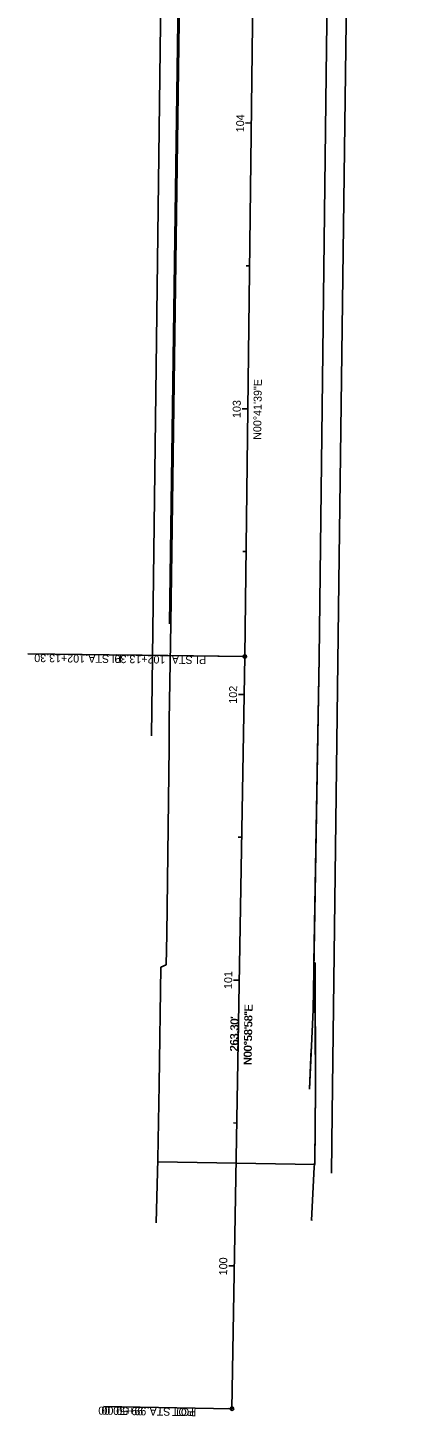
# Model space of a CAD drawing. Extents: x 1652464 to 1652601, y 605963 to 608618.
# Drawn here: x 1652463.9 to 1652601.5, y 605963.2 to 606449.1 of the extents above; entities that cross this region are included whole.
import ezdxf

# ---------------------------------------------------------------- set-up
doc = ezdxf.new("R2010")
doc.units = 0
for name, color, linetype in [('BD_X_Building', 7, 'Continuous'), ('BR_X_SV_Abut', 7, 'Continuous'), ('Default', 7, 'Continuous'), ('DR_X_Erosion_Control', 7, 'Continuous'), ('GE_X_Cells', 7, 'Continuous'), ('PV_X_Curb', 7, 'Continuous'), ('PV_X_Steps', 7, 'Continuous'), ('PV_X_Walk', 7, 'Continuous'), ('SV_P_Mon_Cells_Set', 7, 'Continuous'), ('SV_X_Control_Cells_Found', 7, 'Continuous'), ('SV_X_Shot_Marker', 7, 'Continuous'), ('UT_X_Gas', 7, 'Continuous'), ('UT_X_Water_Cells', 7, 'Continuous'), ('VG_X_Cells', 7, 'Continuous'), ('VG_X_Flower_Bed', 7, 'Continuous'), ('VG_X_Shrub_Line_Lt', 7, 'Continuous')]:
    doc.layers.add(name, color=color, linetype=linetype)

msp = doc.modelspace()

# ---------------------------------------------------------------- linework, layer by layer
at = {"layer": 'BD_X_Building'}
msp.add_lwpolyline([(1652507.27, 606201.32), (1652514.36, 606755.06), (1652515.19, 606820.32), (1652516.55, 606927.44), (1652537.47, 608602.59)], dxfattribs=at)
at = {"layer": 'Default'}
for p, q in [((1652537.06, 606057.13), (1652537.05, 606056.93)), ((1652536.99, 606053.42), (1652536.98, 606052.81))]:
    msp.add_line(p, q, dxfattribs=at)
at = {"layer": 'GE_X_Cells'}
for p, q in [((1652568.47, 606432.68), (1652569.53, 606520.3)), ((1652568.47, 606432.68), (1652569.53, 606520.3)), ((1652568.47, 606432.68), (1652569.53, 606520.3)), ((1652568.47, 606432.68), (1652569.53, 606520.3)), ((1652568.47, 606432.68), (1652569.53, 606520.3)), ((1652568.47, 606432.68), (1652569.53, 606520.3)), ((1652514.05, 606240.46), (1652517.12, 606459.77)), ((1652566, 606228.68), (1652568.47, 606432.68)), ((1652566, 606228.68), (1652568.47, 606432.68)), ((1652566, 606228.68), (1652568.47, 606432.68)), ((1652566, 606228.68), (1652568.47, 606432.68)), ((1652566, 606228.68), (1652568.47, 606432.68)), ((1652566, 606228.68), (1652568.47, 606432.68)), ((1652513.54, 606206.56), (1652514.05, 606240.46)), ((1652563.89, 606105.39), (1652566, 606228.68)), ((1652563.89, 606105.39), (1652566, 606228.68)), ((1652564.17, 606121.81), (1652566, 606228.68)), ((1652564.17, 606121.81), (1652566, 606228.68)), ((1652564.17, 606121.81), (1652566, 606228.68)), ((1652564.17, 606121.81), (1652566, 606228.68)), ((1652513.48, 606197.48), (1652513.54, 606206.56)), ((1652512.65, 606131.81), (1652513.48, 606197.48)), ((1652512.46, 606121.15), (1652512.65, 606131.81)), ((1652509.93, 606079.27), (1652510.53, 606120.34)), ((1652510.53, 606120.34), (1652512.46, 606121.15)), ((1652564.61, 606121.81), (1652564.17, 606121.81)), ((1652564.76, 606077.51), (1652564.61, 606121.81)), ((1652562.66, 606077.59), (1652563.89, 606105.39)), ((1652562.66, 606077.59), (1652563.89, 606105.39)), ((1652562.66, 606077.59), (1652563.28, 606091.74)), ((1652509.55, 606053.1), (1652509.93, 606079.27)), ((1652562.66, 606077.59), (1652562.66, 606077.68)), ((1652564.56, 606052.23), (1652564.76, 606077.51)), ((1652508.95, 606030.88), (1652509.55, 606053.1)), ((1652564.35, 606050.39), (1652564.56, 606052.23)), ((1652563.4, 606031.63), (1652564.35, 606050.39)), ((1652563.4, 606031.63), (1652563.42, 606032.07))]:
    msp.add_line(p, q, dxfattribs=at)
msp.add_lwpolyline([(1652564.55, 606051.31), (1652564.76, 606077.51), (1652564.64, 606101.8), (1652564.17, 606121.81)], dxfattribs=at)
at = {"layer": 'PV_X_Curb'}
for p, q in [((1652540.01, 606229.06), (1652551.76, 607199.34)), ((1652535.49, 605965.8), (1652540.01, 606229.06)), ((1652509.53, 606052.25), (1652564.55, 606051.31))]:
    msp.add_line(p, q, dxfattribs=at)
at = {"layer": 'PV_X_Steps'}
msp.add_lwpolyline([(1652570.42, 606048.23), (1652570.59, 606069.16), (1652572.96, 606254.92), (1652575.24, 606433.07), (1652576.4, 606523.06), (1652578.06, 606652.96), (1652579.12, 606736.34), (1652580.12, 606814.04), (1652581.65, 606935.48), (1652585.26, 607224.58), (1652586.28, 607305.92), (1652588.75, 607503.82), (1652591.34, 607710.88), (1652594.35, 607951.77), (1652594.72, 607981.92), (1652597.89, 608234.94), (1652601.47, 608521.97)], dxfattribs=at)
at = {"layer": 'PV_X_Walk'}
msp.add_line((1652513.55, 606240.47), (1652516.62, 606459.78), dxfattribs=at)
at = {"layer": 'SV_X_Control_Cells_Found'}
for p, q in [((1652540.01, 606229.06), (1652551.76, 607199.34)), ((1652540.01, 606229.06), (1652551.76, 607199.34)), ((1652535.49, 605965.8), (1652540.01, 606229.06)), ((1652535.49, 605965.8), (1652540.01, 606229.06))]:
    msp.add_line(p, q, dxfattribs=at)
at = {"layer": 'SV_X_Shot_Marker'}
for q in [(1652463.93, 606229.98), (1652495.01, 606229.6)]:
    msp.add_line((1652540.01, 606229.06), q, dxfattribs=at)
msp.add_circle((1652540.01, 606229.06), 0.6, dxfattribs=at)
msp.add_circle((1652540.01, 606229.06), 0.6, dxfattribs=at)
at = {"layer": 'UT_X_Gas'}
msp.add_line((1652535.49, 605965.8), (1652490.5, 605966.57), dxfattribs=at)
msp.add_circle((1652535.49, 605965.8), 0.6, dxfattribs=at)
at = {"layer": 'VG_X_Cells'}
for p, q in [((1652542.27, 606415.74), (1652540.27, 606415.77)), ((1652541.66, 606365.75), (1652540.46, 606365.76)), ((1652541.06, 606315.75), (1652539.06, 606315.77)), ((1652540.45, 606265.75), (1652539.25, 606265.77)), ((1652539.78, 606215.76), (1652537.78, 606215.79)), ((1652538.92, 606165.77), (1652537.72, 606165.79)), ((1652538.06, 606115.77), (1652536.06, 606115.81)), ((1652537.2, 606065.78), (1652536.01, 606065.8)), ((1652536.35, 606015.79), (1652534.35, 606015.82)), ((1652535.49, 605965.8), (1652534.29, 605965.82))]:
    msp.add_line(p, q, dxfattribs=at)
at = {"layer": 'VG_X_Flower_Bed'}
for p, q in [((1652540.01, 606229.06), (1652495.01, 606229.6)), ((1652535.49, 605965.8), (1652490.5, 605966.57))]:
    msp.add_line(p, q, dxfattribs=at)
for centre in [(1652540.01, 606229.06), (1652535.49, 605965.8)]:
    msp.add_circle(centre, 0.6, dxfattribs=at)
at = {"layer": 'VG_X_Shrub_Line_Lt'}
for p, q in [((1652542.27, 606415.74), (1652541.07, 606415.76)), ((1652541.06, 606315.75), (1652539.86, 606315.76)), ((1652539.78, 606215.76), (1652538.58, 606215.78)), ((1652538.06, 606115.77), (1652536.86, 606115.79)), ((1652536.35, 606015.79), (1652534.35, 606015.82))]:
    msp.add_line(p, q, dxfattribs=at)

# ---------------------------------------------------------------- texts
at = {"layer": 'BR_X_SV_Abut'}
msp.add_text('N00°58\'58"E', height=2.8, rotation=89.0173, dxfattribs=at).set_placement((1652542.36, 606086.17))
at = {"layer": 'DR_X_Erosion_Control'}
msp.add_text("263.30'", height=2.8, rotation=89.0173, dxfattribs=at).set_placement((1652537.59, 606090.94))
at = {"layer": 'SV_P_Mon_Cells_Set'}
for s, rotation, p in [('N00°41\'39"E', 89.3059, (1652545.72, 606304.86)), ('N00°58\'58"E', 89.0173, (1652542.35, 606085.98))]:
    msp.add_text(s, height=2.8, rotation=rotation, dxfattribs=at).set_placement(p)
at = {"layer": 'SV_X_Shot_Marker'}
for s, p in [('102+13.30', (1652484.05, 606229.69)), (' STA. ', (1652493.5, 606229.58)), ('PI', (1652496.89, 606229.54))]:
    msp.add_text(s, height=2.8, rotation=179.3059, dxfattribs=at).set_placement(p)
at = {"layer": 'UT_X_Gas'}
for s, p in [('99+50.00', (1652505.52, 605966.27)), (' STA. ', (1652514.97, 605966.11)), ('POT', (1652522.17, 605965.98))]:
    msp.add_text(s, height=2.8, rotation=179.0173, dxfattribs=at).set_placement(p)
at = {"layer": 'UT_X_Water_Cells'}
msp.add_text("263.30'", height=2.8, rotation=89.0173, dxfattribs=at).set_placement((1652537.59, 606090.75))
at = {"layer": 'VG_X_Cells'}
for s, rotation, p in [('104', 89.3059, (1652539.73, 606412.5)), ('103', 89.3059, (1652538.52, 606312.51)), ('102', 89.0173, (1652537.22, 606212.52)), ('101', 89.0173, (1652535.51, 606112.67)), ('100', 89.0173, (1652533.79, 606012.48))]:
    msp.add_text(s, height=2.8, rotation=rotation, dxfattribs=at).set_placement(p)
at = {"layer": 'VG_X_Flower_Bed'}
for s, rotation, p in [('102+13.30', 179.3059, (1652512.18, 606229.35)), (' STA. ', 179.3059, (1652522.76, 606229.22)), ('PI', 179.3059, (1652526.46, 606229.18)), ('99+50.00', 179.0173, (1652504.41, 605966.28)), (' STA. ', 179.0173, (1652514.99, 605966.1)), ('POT', 179.0173, (1652523.03, 605965.96))]:
    msp.add_text(s, height=2.8, rotation=rotation, dxfattribs=at).set_placement(p)
at = {"layer": 'VG_X_Shrub_Line_Lt'}
msp.add_text('100', height=2.8, rotation=89.0173, dxfattribs=at).set_placement((1652533.75, 606012.49))

doc.saveas('drawing.dxf')
